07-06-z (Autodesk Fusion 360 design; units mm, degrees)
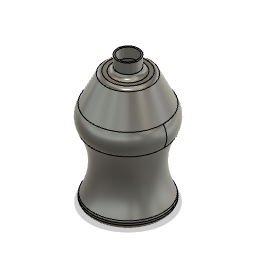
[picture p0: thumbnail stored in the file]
sketch "スケッチ1" plane through (0, 0, 0) normal (0, 1, 0) x axis (1, 0, 0)
  circle C1 centre (0, 0) radius 25
  point P1 (0, 0)
  point P2 (0, 0)
  coincident P1 P2
  dimension "d1" diameter C1 = 50
extrude "押し出し1" new body sketch "スケッチ1" along normal blind 5
work_plane "作業平面1" AlongDistance 20
sketch "スケッチ2" plane through (0, 25, 0) normal (0, 1, 0) x axis (1, 0, 0)
  circle C1 centre (0, 0) radius 20
  point P1 (0, 0)
  point P2 (0, 0)
  coincident P1 P2
  dimension "d5" diameter C1 = 40
work_plane "作業平面2" AlongDistance 20
sketch "スケッチ3" plane through (0, 45, 0) normal (0, 1, 0) x axis (1, 0, 0)
  circle C1 centre (0, 0) radius 25
loft "ロフト1" sketch "スケッチ2" + "スケッチ3"
work_plane "作業平面3" AlongDistance 15
sketch "スケッチ4" plane through (0, 60, 0) normal (0, 1, 0) x axis (1, 0, 0)
  circle C1 centre (0, 0) radius 25
sketch "スケッチ5" plane through (0, 0, 0) normal (0, 0, 1) x axis (1, 0, 0)
  line L1 (-25, 60) -> (25, 60)
  line L2 (25, 45) -> (-25, 45)
  arc A1 centre (-14.3816, 52.5) radius 13 clockwise from (-25, 45) to (-25, 60)
  arc A2 centre (14.3816, 52.5) radius 13 clockwise from (25, 60) to (25, 45)
  point P2 (-25, 60)
  point P9 (-25, 60)
  point P3 (-25, 45)
  point P10 (-25, 45)
  point P5 (25, 60)
  point P8 (25, 60)
  point P6 (25, 45)
  point P11 (25, 45)
  coincident P2 P9
  coincident P3 P10
  coincident P5 P8
  coincident P6 P11
  equal A1 A2
  dimension "d8" radius A1 = 13
sketch "スケッチ6" plane through (0, 0, 0) normal (1, 0, 0) x axis (0, 0, -1)
  line L1 (-25, 60) -> (25, 60)
  line L2 (25, 45) -> (-25, 45)
  arc A1 centre (-14.3816, 52.5) radius 13 clockwise from (-25, 45) to (-25, 60)
  arc A2 centre (14.3816, 52.5) radius 13 clockwise from (25, 60) to (25, 45)
  point P2 (-25, 60)
  point P9 (-25, 60)
  point P3 (-25, 45)
  point P10 (-25, 45)
  point P6 (25, 45)
  point P11 (25, 45)
  point P5 (25, 60)
  point P8 (25, 60)
  coincident P2 P9
  coincident P3 P10
  coincident P6 P11
  coincident P5 P8
  equal A1 A2
  dimension "d9" radius A1 = 13
loft "ロフト2" sketch "スケッチ4"
work_plane "作業平面4" AlongDistance 20
sketch "スケッチ7" plane through (0, 80, 0) normal (0, 1, 0) x axis (1, 0, 0)
  circle C1 centre (0, 0) radius 15
  point P1 (0, 0)
  point P2 (0, 0)
  coincident P1 P2
  dimension "d12" diameter C1 = 30
loft "ロフト3" sketch "スケッチ7"
sketch "スケッチ8" plane through (0, 80, 0) normal (0, 1, 0) x axis (-1, 0, 0)
  circle C1 centre (0, 0) radius 15
  circle C2 centre (0, 0) radius 7.5
  point P1 (0, 0)
  point P3 (0, 0)
  coincident P1 P3
  dimension "d13" diameter C2 = 15
extrude "押し出し2" add sketch "スケッチ8" profile of C2 along normal blind 10
fillet "フィレット" radius 3
shell "シェル" innerThickness 1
